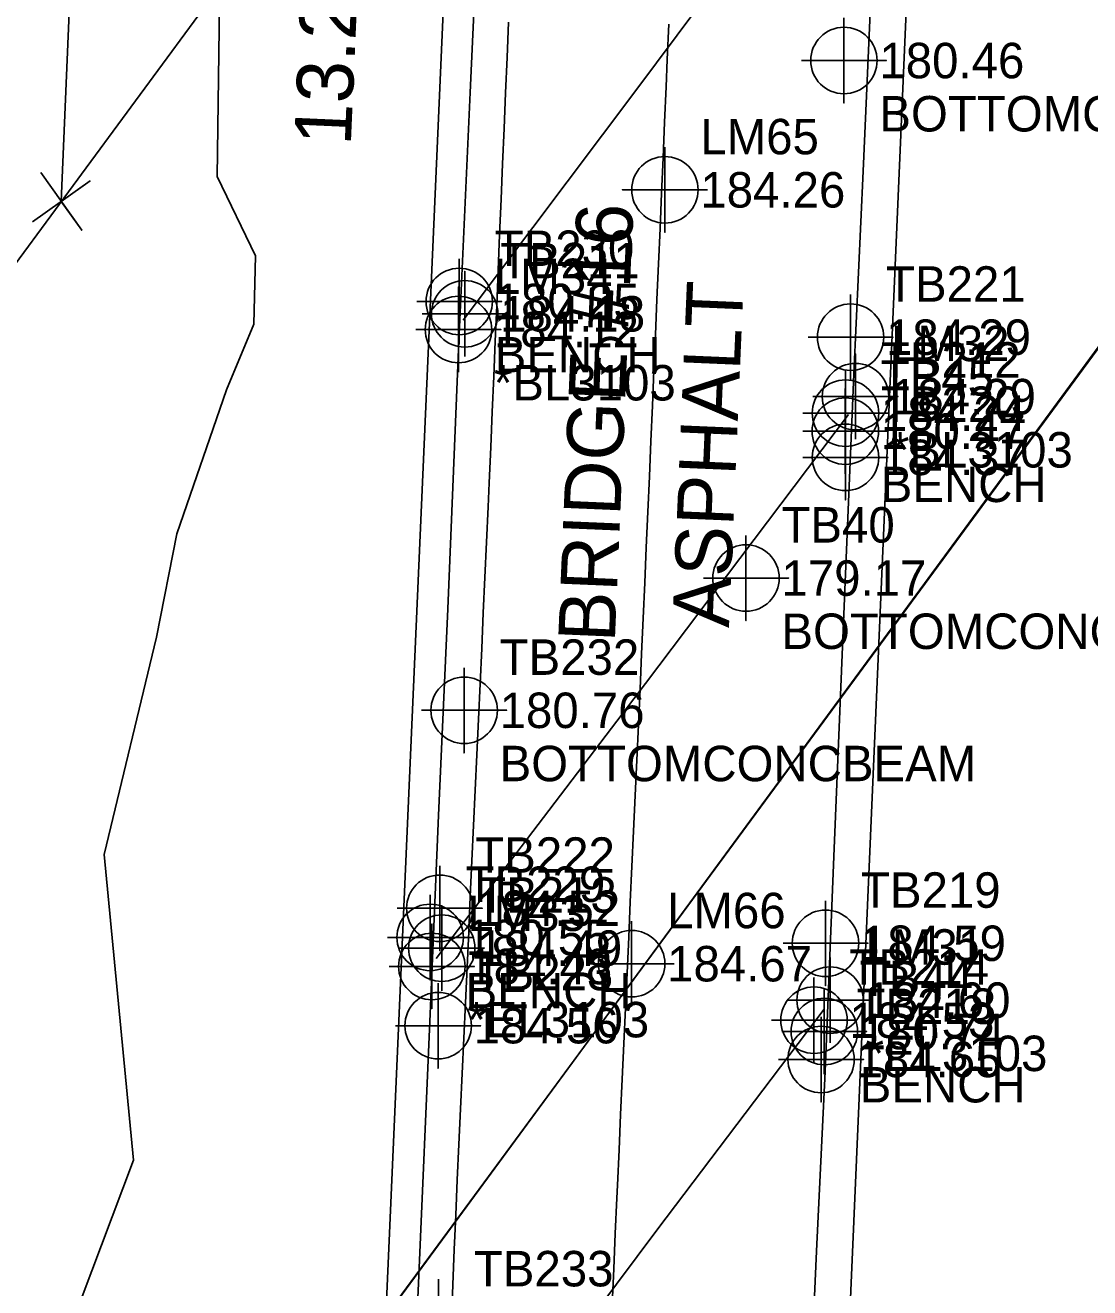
# Model space of a CAD drawing. Extents: x 2262665 to 2270527, y 505476 to 514960.
# Drawn here: x 2266230.3 to 2266305.3, y 510501.2 to 510590.2 of the extents above; entities that cross this region are included whole.
import ezdxf

# ---------------------------------------------------------------- set-up
doc = ezdxf.new("R2010")
doc.units = 0
for name, color, linetype in [('Default Symbol CELL', 7, 'Continuous'), ('Default Symbol Cogo Comment', 7, 'Continuous'), ('Default Symbol Cogo Elevation', 7, 'Continuous'), ('Default Symbol Cogo Number', 7, 'Continuous'), ('Exist Guardrail', 7, 'Continuous'), ('Exist Horizontal Alignment', 7, 'Continuous'), ('Exist Property Corner CELL', 7, 'Continuous'), ('Exist Railroads Standard Gauge', 7, 'Continuous'), ('Exist Right of Way Control of Access Line', 7, 'Continuous'), ('Exist Right of Way Line', 7, 'Continuous'), ('Exist Roads EOT', 7, 'Continuous'), ('Exist Roads EOT Cogo Elevation', 7, 'Continuous'), ('Exist Roads EOT Cogo Number', 7, 'Continuous'), ('Exist Roads EOT Cogo Point CELL', 7, 'Continuous'), ('Exist Structure Major Bridge Seam', 7, 'Continuous'), ('Exist Structure Major Bridge Seam Cogo Comment', 7, 'Continuous'), ('Exist Structure Major Bridge Seam Cogo Elevation', 7, 'Continuous'), ('Exist Structure Major Bridge Seam Cogo Number', 7, 'Continuous'), ('Exist Structure Major Bridge Seam Cogo Point CELL', 7, 'Continuous'), ('Exist Structure Major Bridge WW Text', 7, 'Continuous'), ('Exist Structure Major Deck Tunnel Box Culvert', 7, 'Continuous'), ('Exist Structure Major Deck Tunnel Box Culvert Text', 7, 'Continuous'), ('Exist Structure Minor Drop Inlet Cogo Elevation', 7, 'Continuous'), ('Exist Structure Minor Drop Inlet Cogo Number', 7, 'Continuous'), ('Exist Structure Minor Drop Inlet Cogo Point CELL', 7, 'Continuous'), ('Exist Vegetation Woods Line', 7, 'Continuous')]:
    doc.layers.add(name, color=color, linetype=linetype)

msp = doc.modelspace()

# ---------------------------------------------------------------- linework, layer by layer
at = {"layer": 'Default Symbol CELL'}
for points in [[(2266287.997, 510590.713), (2266287.997, 510584.713), (2266287.997, 510587.713), (2266290.997, 510587.713), (2266284.997, 510587.713)], [(2266260.863, 510573.73), (2266260.863, 510567.73), (2266260.863, 510570.73), (2266263.863, 510570.73), (2266257.863, 510570.73)], [(2266288.093, 510564.588), (2266288.093, 510558.588), (2266288.093, 510561.588), (2266291.093, 510561.588), (2266285.093, 510561.588)], [(2266281.09, 510554.231), (2266281.09, 510548.231), (2266281.09, 510551.231), (2266284.09, 510551.231), (2266278.09, 510551.231)], [(2266261.211, 510544.909), (2266261.211, 510538.909), (2266261.211, 510541.909), (2266264.211, 510541.909), (2266258.211, 510541.909)], [(2266258.812, 510528.9), (2266258.812, 510522.9), (2266258.812, 510525.9), (2266261.812, 510525.9), (2266255.812, 510525.9)], [(2266286.612, 510522.267), (2266286.612, 510516.267), (2266286.612, 510519.267), (2266289.612, 510519.267), (2266283.612, 510519.267)], [(2266259.395, 510501.8), (2266259.395, 510495.8), (2266259.395, 510498.8), (2266262.395, 510498.8), (2266256.395, 510498.8)]]:
    msp.add_lwpolyline(points, dxfattribs=at)
for centre in [(2266287.997, 510587.713), (2266260.863, 510570.73), (2266288.093, 510561.588), (2266281.09, 510551.231), (2266261.211, 510541.909), (2266258.812, 510525.9), (2266286.612, 510519.267)]:
    msp.add_circle(centre, 2.344, dxfattribs=at)
at = {"layer": 'Exist Guardrail'}
msp.add_line((2266250.799, 510388.262), (2266260.579, 510610.518), dxfattribs=at)
msp.add_lwpolyline([(2266297.838, 510666.305), (2266295.849, 510665.082), (2266295.379, 510664.263), (2266295.235, 510663.319), (2266295.159, 510660.268), (2266295.244, 510656.94), (2266285.654, 510435.804)], dxfattribs=at)
at = {"layer": 'Exist Horizontal Alignment'}
msp.add_line((2266115.369, 510308.344), (2266484.608, 510810.549), dxfattribs=at)
at = {"layer": 'Exist Property Corner CELL'}
msp.add_line((2266232.793, 510577.784), (2266232.793, 510577.784), dxfattribs=at)
msp.add_lwpolyline([(2266231.345, 510579.821), (2266234.241, 510575.746), (2266232.793, 510577.784), (2266234.831, 510579.232), (2266230.755, 510576.335)], dxfattribs=at)
at = {"layer": 'Exist Railroads Standard Gauge'}
msp.add_lwpolyline([(2266050.126, 510219.701), (2266084.793, 510266.487), (2266115.405, 510308.449), (2266145.346, 510349.147), (2266177.142, 510392.251), (2266205.29, 510430.675), (2266238.555, 510475.952), (2266285.007, 510539.009), (2266316.093, 510581.207), (2266370.928, 510656.017), (2266407.404, 510705.524), (2266453.51, 510768.358), (2266484.598, 510810.492), (2266484.598, 510810.492), (2266581.191, 510941.594), (2266616.47, 510989.01)], dxfattribs=at)
at = {"layer": 'Exist Right of Way Control of Access Line'}
msp.add_line((2266232.793, 510577.784), (2266283.349, 511801.455), dxfattribs=at)
at = {"layer": 'Exist Right of Way Line'}
msp.add_line((2265436.986, 509495.399), (2266823.179, 511380.773), dxfattribs=at)
at = {"layer": 'Exist Roads EOT'}
for points in [[(2266260.315, 510498.903), (2266260.416, 510501.401), (2266260.517, 510503.899), (2266260.614, 510506.315), (2266260.729, 510508.813), (2266260.843, 510511.31), (2266260.958, 510513.807), (2266261.072, 510516.305), (2266261.187, 510518.802), (2266261.302, 510521.299), (2266261.416, 510523.797), (2266261.531, 510526.294), (2266261.645, 510528.791), (2266261.76, 510531.289), (2266261.874, 510533.786), (2266261.989, 510536.283), (2266262.103, 510538.781), (2266262.218, 510541.278), (2266262.333, 510543.775), (2266262.447, 510546.273), (2266262.562, 510548.77), (2266262.676, 510551.267), (2266262.791, 510553.765), (2266262.905, 510556.262), (2266262.983, 510557.951), (2266263.087, 510560.449), (2266263.191, 510562.947), (2266263.296, 510565.444), (2266263.4, 510567.942), (2266263.504, 510570.44), (2266263.608, 510572.937), (2266263.712, 510575.435), (2266263.817, 510577.933), (2266263.921, 510580.43), (2266264.025, 510582.928), (2266264.129, 510585.426), (2266264.234, 510587.923), (2266264.338, 510590.421)], [(2266271.645, 510500.03), (2266271.757, 510502.528), (2266271.869, 510505.025), (2266271.981, 510507.523), (2266272.021, 510508.427), (2266272.135, 510510.924), (2266272.249, 510513.422), (2266272.363, 510515.919), (2266272.476, 510518.416), (2266272.59, 510520.914), (2266272.704, 510523.411), (2266272.817, 510525.908), (2266272.931, 510528.406), (2266273.045, 510530.903), (2266273.159, 510533.401), (2266273.272, 510535.898), (2266273.386, 510538.395), (2266273.5, 510540.893), (2266273.614, 510543.39), (2266273.727, 510545.887), (2266273.842, 510548.397), (2266273.949, 510550.894), (2266274.057, 510553.392), (2266274.165, 510555.89), (2266274.272, 510558.387), (2266274.38, 510560.885), (2266274.488, 510563.382), (2266274.595, 510565.88), (2266274.703, 510568.378), (2266274.811, 510570.875), (2266274.919, 510573.373), (2266275.026, 510575.87), (2266275.134, 510578.368), (2266275.242, 510580.865), (2266275.349, 510583.363), (2266275.457, 510585.861), (2266275.54, 510587.779), (2266275.636, 510590.277)]]:
    msp.add_lwpolyline(points, dxfattribs=at)
at = {"layer": 'Exist Roads EOT Cogo Point CELL'}
for points in [[(2266275.37, 510581.601), (2266275.37, 510575.601), (2266275.37, 510578.601), (2266272.37, 510578.601), (2266278.37, 510578.601)], [(2266273.025, 510527.047), (2266273.025, 510521.047), (2266273.025, 510524.047), (2266270.025, 510524.047), (2266276.025, 510524.047)]]:
    msp.add_lwpolyline(points, dxfattribs=at)
for centre in [(2266275.37, 510578.601), (2266273.025, 510524.047)]:
    msp.add_circle(centre, 2.344, dxfattribs=at)
at = {"layer": 'Exist Structure Major Bridge Seam'}
for points in [[(2266290.329, 510608.368), (2266273.393, 510585.692), (2266261.151, 510569.42)], [(2266288.329, 510562.76), (2266273.997, 510543.8), (2266259.233, 510524.405)], [(2266286.6, 510520.84), (2266274.868, 510505.363), (2266260.152, 510485.67), (2266257.362, 510482.048)]]:
    msp.add_lwpolyline(points, dxfattribs=at)
at = {"layer": 'Exist Structure Major Bridge Seam Cogo Point CELL'}
for points in [[(2266258.25, 510569.86), (2266264.25, 510569.86), (2266261.25, 510569.86), (2266261.25, 510572.86), (2266261.25, 510566.86)], [(2266257.809, 510568.75), (2266263.809, 510568.75), (2266260.809, 510568.75), (2266260.809, 510571.75), (2266260.809, 510565.75)], [(2266285.814, 510564.022), (2266291.814, 510564.022), (2266288.814, 510564.022), (2266288.814, 510567.022), (2266288.814, 510561.022)], [(2266285.108, 510562.856), (2266291.108, 510562.856), (2266288.108, 510562.856), (2266288.108, 510565.856), (2266288.108, 510559.856)], [(2266256.631, 510525.145), (2266262.631, 510525.145), (2266259.631, 510525.145), (2266259.631, 510528.145), (2266259.631, 510522.145)], [(2266255.931, 510523.854), (2266261.931, 510523.854), (2266258.931, 510523.854), (2266258.931, 510526.854), (2266258.931, 510520.854)], [(2266284.021, 510521.477), (2266290.021, 510521.477), (2266287.021, 510521.477), (2266287.021, 510524.477), (2266287.021, 510518.477)], [(2266282.884, 510520.062), (2266288.884, 510520.062), (2266285.884, 510520.062), (2266285.884, 510523.062), (2266285.884, 510517.062)]]:
    msp.add_lwpolyline(points, dxfattribs=at)
for centre in [(2266261.25, 510569.86), (2266260.809, 510568.75), (2266288.814, 510564.022), (2266288.108, 510562.856), (2266259.631, 510525.145), (2266258.931, 510523.854), (2266287.021, 510521.477), (2266285.884, 510520.062)]:
    msp.add_circle(centre, 2.344, dxfattribs=at)
at = {"layer": 'Exist Structure Major Deck Tunnel Box Culvert'}
msp.add_lwpolyline([(2266285.136, 510483.131), (2266286.056, 510503.78), (2266286.669, 510516.455), (2266287.294, 510531.608), (2266288.029, 510549.809), (2266288.701, 510565.635), (2266289.346, 510579.92), (2266289.982, 510594.288), (2266290.817, 510613.993), (2266291.518, 510631.252), (2266292.331, 510648.73), (2266292.592, 510654.329), (2266281.127, 510639.038), (2266268.999, 510622.475), (2266262.961, 510614.382), (2266262.387, 510601.842), (2266261.623, 510585.453), (2266260.808, 510567.358), (2266260.064, 510549.074), (2266259.395, 510534.489), (2266258.824, 510520.525), (2266257.98, 510501.532), (2266257.184, 510483.844)], dxfattribs=at)
at = {"layer": 'Exist Structure Minor Drop Inlet Cogo Point CELL'}
for points in [[(2266288.467, 510571.21), (2266288.467, 510565.21), (2266288.467, 510568.21), (2266291.467, 510568.21), (2266285.467, 510568.21)], [(2266288.108, 510562.739), (2266288.108, 510556.739), (2266288.108, 510559.739), (2266291.108, 510559.739), (2266285.108, 510559.739)], [(2266259.492, 510530.955), (2266259.492, 510524.955), (2266259.492, 510527.955), (2266262.492, 510527.955), (2266256.492, 510527.955)], [(2266286.7, 510528.488), (2266286.7, 510522.488), (2266286.7, 510525.488), (2266289.7, 510525.488), (2266283.7, 510525.488)], [(2266259.377, 510522.678), (2266259.377, 510516.678), (2266259.377, 510519.678), (2266262.377, 510519.678), (2266256.377, 510519.678)], [(2266286.387, 510520.298), (2266286.387, 510514.298), (2266286.387, 510517.298), (2266289.387, 510517.298), (2266283.387, 510517.298)]]:
    msp.add_lwpolyline(points, dxfattribs=at)
for centre in [(2266288.467, 510568.21), (2266288.108, 510559.739), (2266259.492, 510527.955), (2266286.7, 510525.488), (2266259.377, 510519.678), (2266286.387, 510517.298)]:
    msp.add_circle(centre, 2.344, dxfattribs=at)
at = {"layer": 'Exist Vegetation Woods Line'}
msp.add_lwpolyline([(2266251.285, 510670.915), (2266250.448, 510659.451), (2266249.544, 510639.215), (2266248.106, 510632.96), (2266245.226, 510624.86), (2266245.197, 510617.691), (2266245.945, 510612.056), (2266244.307, 510602.832), (2266244.116, 510595.529), (2266243.947, 510591.697), (2266243.792, 510579.534), (2266246.486, 510573.943), (2266246.377, 510569.135), (2266244.453, 510564.494), (2266240.937, 510554.361), (2266239.514, 510547.06), (2266235.817, 510531.751), (2266237.883, 510510.198), (2266232.702, 510496.415)], dxfattribs=at)

# ---------------------------------------------------------------- texts
at = {"layer": 'Default Symbol Cogo Comment'}
for s, p in [('BOTTOMCONCBEAM', (2266290.497, 510582.713)), ('BENCH', (2266263.363, 510565.73)), ('BENCH', (2266290.593, 510556.588)), ('BOTTOMCONCBEAM', (2266283.59, 510546.231)), ('BOTTOMCONCBEAM', (2266263.711, 510536.909)), ('BENCH', (2266261.312, 510520.9)), ('BENCH', (2266289.112, 510514.267))]:
    msp.add_text(s, height=2.5, dxfattribs=at).set_placement(p)
at = {"layer": 'Default Symbol Cogo Elevation'}
for s, p in [('180.46', (2266290.497, 510586.463)), ('180.25', (2266263.363, 510569.48)), ('180.47', (2266290.593, 510560.338)), ('179.17', (2266283.59, 510549.981)), ('180.76', (2266263.711, 510540.659)), ('180.55', (2266261.312, 510524.65)), ('180.74', (2266289.112, 510518.017))]:
    msp.add_text(s, height=2.5, dxfattribs=at).set_placement(p)
at = {"layer": 'Default Symbol Cogo Number'}
for s, p in [('TB230', (2266263.363, 510573.23)), ('TB45', (2266290.593, 510564.088)), ('TB40', (2266283.59, 510553.731)), ('TB232', (2266263.711, 510544.409)), ('TB229', (2266261.312, 510528.4)), ('TB44', (2266289.112, 510521.767)), ('TB233', (2266261.895, 510501.3))]:
    msp.add_text(s, height=2.5, dxfattribs=at).set_placement(p)
at = {"layer": 'Exist Roads EOT Cogo Elevation'}
for s, p in [('184.26', (2266277.87, 510577.351)), ('184.67', (2266275.525, 510522.797))]:
    msp.add_text(s, height=2.5, dxfattribs=at).set_placement(p)
at = {"layer": 'Exist Roads EOT Cogo Number'}
for s, p in [('LM65', (2266277.87, 510581.101)), ('LM66', (2266275.525, 510526.547))]:
    msp.add_text(s, height=2.5, dxfattribs=at).set_placement(p)
at = {"layer": 'Exist Structure Major Bridge Seam Cogo Comment'}
for s, p in [('*BL3103', (2266263.309, 510563.75)), ('*BL3103', (2266291.314, 510559.022)), ('*EL3103', (2266261.431, 510518.854)), ('*EL3103', (2266289.521, 510516.477))]:
    msp.add_text(s, height=2.5, dxfattribs=at).set_placement(p)
at = {"layer": 'Exist Structure Major Bridge Seam Cogo Elevation'}
for s, p in [('184.18', (2266263.75, 510568.61)), ('184.12', (2266263.309, 510567.5)), ('184.29', (2266291.314, 510562.772)), ('184.24', (2266290.608, 510561.606)), ('184.49', (2266262.131, 510523.895)), ('184.48', (2266261.431, 510522.604)), ('184.60', (2266289.521, 510520.227)), ('184.53', (2266288.384, 510518.812))]:
    msp.add_text(s, height=2.5, dxfattribs=at).set_placement(p)
at = {"layer": 'Exist Structure Major Bridge Seam Cogo Number'}
for s, p in [('TB211', (2266263.75, 510572.36)), ('LM34', (2266263.309, 510571.25)), ('LM32', (2266291.314, 510566.522)), ('TB212', (2266290.608, 510565.356)), ('TB213', (2266262.131, 510527.645)), ('LM33', (2266261.431, 510526.354)), ('LM31', (2266289.521, 510523.977)), ('TB214', (2266288.384, 510522.562))]:
    msp.add_text(s, height=2.5, dxfattribs=at).set_placement(p)
at = {"layer": 'Exist Structure Major Bridge WW Text'}
msp.add_text("13.2' CONC WW", height=4, rotation=87.48028, dxfattribs=at).set_placement((2266253.212, 510581.681))
at = {"layer": 'Exist Structure Major Deck Tunnel Box Culvert Text'}
for s, p in [('BRIDGE #16', (2266271.835, 510546.663)), ('   ASPHALT', (2266279.697, 510543.254))]:
    msp.add_text(s, height=4, rotation=87.55829, dxfattribs=at).set_placement(p)
at = {"layer": 'Exist Structure Minor Drop Inlet Cogo Elevation'}
for s, p in [('184.29', (2266290.967, 510566.96)), ('184.37', (2266290.608, 510558.489)), ('184.52', (2266261.992, 510526.705)), ('184.59', (2266289.2, 510524.238)), ('184.56', (2266261.877, 510518.428)), ('184.65', (2266288.887, 510516.048))]:
    msp.add_text(s, height=2.5, dxfattribs=at).set_placement(p)
at = {"layer": 'Exist Structure Minor Drop Inlet Cogo Number'}
for s, p in [('TB221', (2266290.967, 510570.71)), ('TB220', (2266290.608, 510562.239)), ('TB222', (2266261.992, 510530.455)), ('TB219', (2266289.2, 510527.988)), ('TB223', (2266261.877, 510522.178)), ('TB218', (2266288.887, 510519.798))]:
    msp.add_text(s, height=2.5, dxfattribs=at).set_placement(p)

doc.saveas('drawing.dxf')
